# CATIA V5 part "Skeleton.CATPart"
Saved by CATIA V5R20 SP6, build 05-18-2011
Part number: Skeleton
Publications: "Upper Boundary Curve", "Middle Boundary Curve", "Lower Boundary Curve", "Upper Guide Curve", "Lower Guide Curve"
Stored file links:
  E:\LCS\20170920\#01 CATIA Lecture Materials\#55 GSD18\#01 CATPart\Skeleton.CATPart

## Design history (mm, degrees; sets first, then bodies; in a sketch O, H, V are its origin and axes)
Set1 "Reference Data"
  Point1 "Center Point": (0, 0, 0)
Set2 "Wireframe Data"
  Circle1: type CtrRad, Start -180, End 0, Center {point type Coord, X -86, Y 0, Z 0}, Support xy-plane, Radius 15, FirstDirection (1, 0, 0)
  Line1: type PtDir, RefPoint {point type Coord, X 0, Y -11, Z 0}, Direction yz-plane, Start 0, End 30
  Circle2: type BitangentRad, Start -180, End 0, Element1 Circle1, Element2 vertex of Line1, Radius 910
  Trim1 "Inner Boundary Curve": Trimmed (Circle1; Circle2; Line1)
  Circle3: type CtrRad, Start -180, End 0, Center {point type Coord, X -86, Y 0, Z 0}, Support xy-plane, Radius 30, FirstDirection (1, 0, 0)
  Line2: type PtDir, RefPoint {point type Coord, X 0, Y -21, Z 0}, Direction yz-plane, Start 0, End 30
  Circle4: type BitangentRad, Start -180, End 0, Element1 Circle3, Element2 vertex of Line2, Radius 380
  Trim2 "Outer Boundary Curve": Trimmed (Circle3; Circle4; Line2)
  Circle5 "Upper Boundary Curve": type CtrRad, Start -285, End -268, Center {point type Coord, X 0, Y 0, Z -600}, Support zx-plane, Radius 600, FirstDirection (-1, 0, 0)
  Circle6 "Middle Boundary Curve": type CtrRad, Start -295, End -268, Center {point type Coord, X 0, Y 0, Z -400}, Support zx-plane, Radius 385, FirstDirection (-1, 0, 0)
  Circle7: type CtrRad, Start -290, End -268, Center {point type Coord, X 0, Y 0, Z -350}, Support zx-plane, Radius 325, FirstDirection (-1, 0, 0)
  Circle8: type CtrRad, Start -300, End -270, Center {point type Coord, X 0, Y 0, Z -350}, Support zx-plane, Radius 310, FirstDirection (-1, 0, 0)
  Point2: type OnPlane, Support xy-plane, H -40, V 0, Direction (1, 0, 0)
  Point3: type OnPlane, Support xy-plane, H -54, V 0, Direction (1, 0, 0)
  Project1: ToProject Point2, Support Circle7, Direction xy-plane
  Project2: ToProject Point3, Support Circle8, Direction xy-plane
  Connect1: Curve1 Circle7, Point1 Project1, Tension1 1, Curve2 Circle8, Point2 Project2, Tension2 1
  Trim3 "Lower Boundary Curve": Trimmed (Circle7; Connect1; Circle8)
  Combine1 "Lower Guide Curve": Curve1 Trim2, Curve2 Circle6
  Combine2 "Upper Guide Curve": Curve1 Trim1, Curve2 Circle5
Body1 (main body)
